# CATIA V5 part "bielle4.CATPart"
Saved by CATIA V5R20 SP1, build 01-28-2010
Part number: Part1.1.2.3.4
Bounding box of the stored display mesh (mm): x 48 to 87, y 0 to 5, z 28.093 to 41.907
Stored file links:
  E:\EDELI\gcausse\Edeli_2012_685_gcausse\bielle4.CATPart
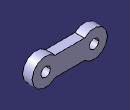
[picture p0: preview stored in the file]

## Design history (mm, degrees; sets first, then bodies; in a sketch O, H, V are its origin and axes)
Parameters
  long = 0.025
  diamtrou = 0.005
Body1 (main body)
  Sketch1 on zx-plane, origin (0, 0, 0), H (-1, 0, 0), V (0, 0, 1)
    line L1 (-59.899, 40) -> (-75.101, 40)
    line L2 (-59.899, 30) -> (-75.101, 30)
    arc A1 centre (-55, 35) radius 7 from (-59.899, 40) to (-59.899, 30) cw
    point P5 (-55, 35)
    point P6 (-50.101, 30)
    arc A2 centre (-80, 35) radius 7 from (-75.101, 40) to (-75.101, 30) ccw
    point P7 (-80, 35)
    circle A3 centre (-55, 35) radius 2.5
    distance P7 L1 = 5
    distance P5 L2 = 5
    distance L2 L1 = 10
    radius A1 = 7
    radius A2 = 7
    distance P5 P7 = 25 {= long}
    radius A3 = 2.5
    horizontal: L1 H, L2 H
    coincidence: A1 P6, P6 L2
  Pad1: profile Sketch1, direction (0, 1, 0), length 5
  Sketch2 on end face of Pad1, origin (0, 5, 0), H (-1, 0, 0), V (0, 0, 1)
    circle A1 centre (-80, 35) radius 2.5
    reference projected arc E1 centre (-80, 35) radius 7 from (-75.101, 40) to (-75.101, 30) ccw from edge [face of Pad1 from Sketch1.A2 | end face of Pad1]
    reference projected arc E2 centre (-80, 35) radius 7 from (-75.101, 40) to (-75.101, 30) ccw from edge [face of Pad1 from Sketch1.A2 | end face of Pad1]
    radius A1 = 2.5
    radius E2 = 7 (reference)
    concentricity: A1 E1
  Pocket1: profile Sketch2, direction (0, -1, 0), length 5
